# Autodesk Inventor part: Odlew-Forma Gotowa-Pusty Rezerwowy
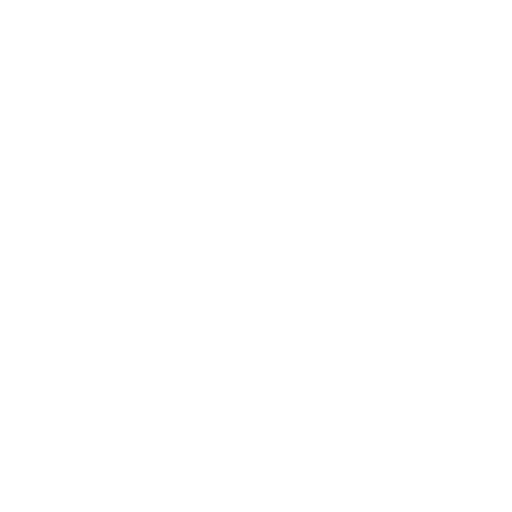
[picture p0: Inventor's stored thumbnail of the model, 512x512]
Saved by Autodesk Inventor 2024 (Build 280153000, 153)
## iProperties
Company: ATC
Shininess: 20.0
Length Units: 11269
Angle Units: 11279
Time Units: 11290
Mass Units: 11283
Length Display Precision: 3
Angle Display Precision: 2
Compacted: True
Created: 2023-03
Part Number: Odlew-Forma Gotowa-Pusty Rezerwowy
Document SubType Name: Modeling
Designer: Andrzej Jaskulski
Material: Kurs-AJ
Density: 1 g/cm^3
Appearance: Przezroczyste - zielone 1
Checked By: A.J.
Engr Approved By: Andrzej Jaskulski
Mfg Approved By: Andrzej Jaskulski
Authority: A.J.
Density: 0.0
Volumn: 0.0
Area: 0.0
PropertySet Name: Model Information
Control State: 0
Master: False
Checked Out: False
Title: A.J.: Kurs R2024-MEP
Author: Andrzej Jaskulski
Revision Number: 1/24
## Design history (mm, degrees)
node "Korpusy bryłowe"
node "Korpusy powierzchniowe"
other parameters: "SZEROKOŚĆ" = 85 [user parameter], "NADDATEK" = 3 [user parameter], "PROMIEŃ" = 2 [user parameter]
